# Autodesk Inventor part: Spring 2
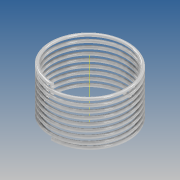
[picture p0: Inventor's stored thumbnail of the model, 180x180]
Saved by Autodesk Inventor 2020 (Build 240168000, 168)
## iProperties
Created: 2019-10
Part Number: Spring 2
Material: Generic
Document SubType Name: Modeling
Designer: yello
Density: 1 g/cm^3
Appearance: Default
Author: yello
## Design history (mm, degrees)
sketch "Sketch1"
  geometry: L1 (0, 0)-(8, 0); L2 (0, 0)-(0, 3.1); C1 r 0.125 at (0, 3.1)
  constraints: 4 end point, 1 centre point, 1 coincident, 1 horizontal, 1 vertical
  dimensions: "d0" = 8 distance of L1.start L1.end; "d1" = 3.1 distance of L1.start L2.end; "d2" = 0.25 diameter of C1
coil "Coil1" sketch "Sketch1" pitch "d3" = 0.45; turns "d5" = 8.5; dims "d4" = 10, "d6" = 0, angle "d7" = 90 deg, angle "d8" = 90 deg, "d9" = 0, "d10" = 0
body "Solid1"
